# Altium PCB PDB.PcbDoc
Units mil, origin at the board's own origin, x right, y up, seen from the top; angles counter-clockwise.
Board outline 4930 x 2490 mil, 2 copper layers (Top Layer, Bottom Layer); 48 components, 33 nets, 136 pads, 994 vias.
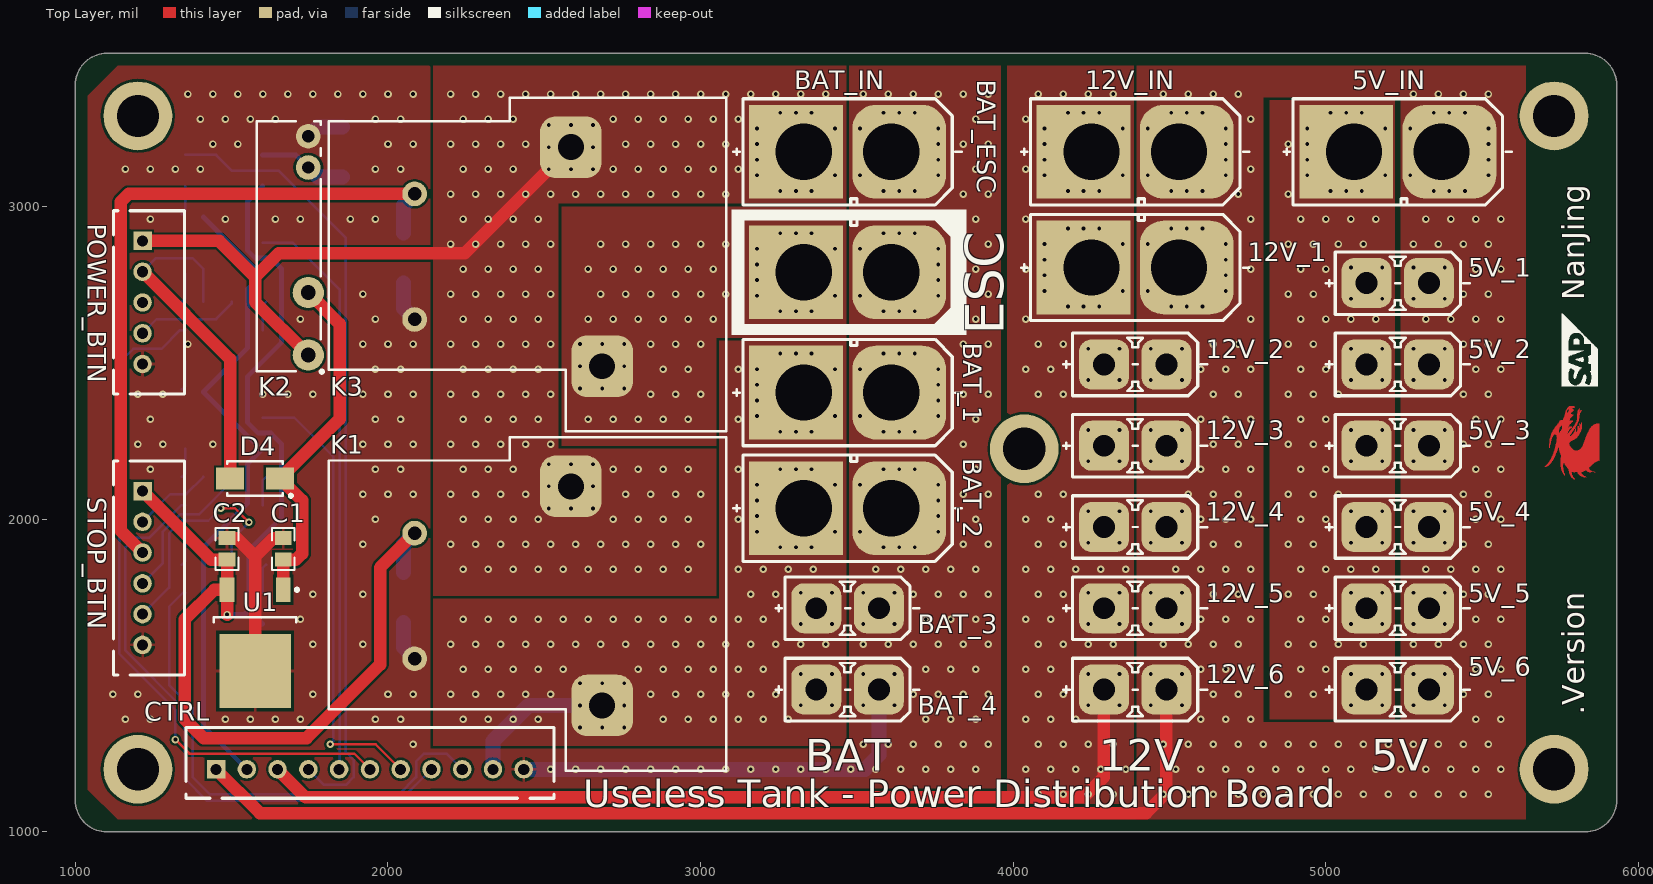
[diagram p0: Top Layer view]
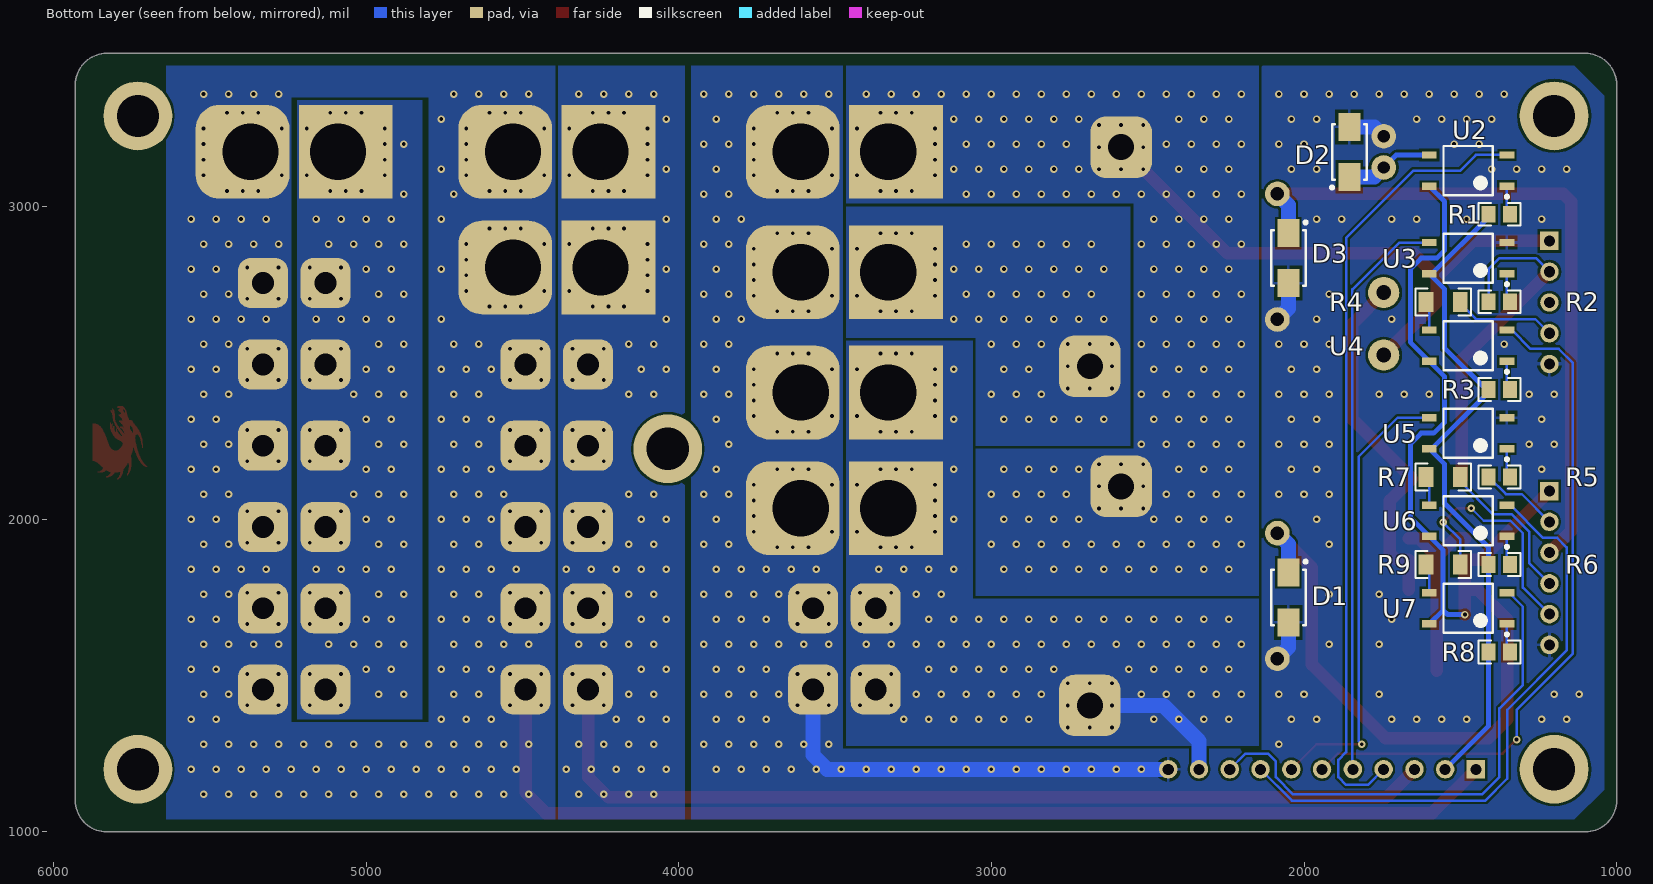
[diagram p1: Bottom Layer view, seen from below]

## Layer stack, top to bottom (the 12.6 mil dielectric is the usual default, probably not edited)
Top Solder: solder mask 0.4, Solder Resist, Dk 3.5
Top Layer: signal copper 1.4
Dielectric 1: dielectric 12.6, FR-4, Dk 4.8
Bottom Layer: signal copper 1.4
Bottom Solder: solder mask 0.4, Solder Resist, Dk 3.5

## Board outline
1100,1000 cw(c1100,1100) 1000,1100 1000,3390 cw(c1100,3390) 1100,3490 5830,3490 cw(c5830,3390) 5930,3390 5930,1100 cw(c5830,1100) 5830,1000

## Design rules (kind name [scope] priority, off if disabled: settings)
Clearance [All] p1: gap=8
ComponentClearance [All] p1: gap=8 collisioncheckmode=3 verticalgap=10 showdistances=FALSE
HoleSize [All] p1: absolutevalues=TRUE maxlimit=200 minlimit=12 maxpercent=80.000 minpercent=20.000
MinimumSolderMaskSliver [All] p1: minsoldermaskwidth=8
PolygonConnect "Full Connect" [IsVia OR (HasFootprint('XT60PB-M') OR HasFootprint('XT60PB-F') OR HasFootprint('XT30UPB-F') OR HasFootprint('HF105F-1') OR HasFootprint('HF49FD/xxx-1Hx1'))] p1: connectstyle=Direct reliefconductorwidth=10 reliefentries=4 polygonreliefangle="90 Angle" airgapwidth=10
PolygonConnect [All] p2: connectstyle=Relief reliefconductorwidth=10 reliefentries=4 polygonreliefangle="90 Angle" airgapwidth=10
RoutingVias [All] p1: holewidth=12 width=24 viastyle="Through Hole" minholewidth=12 minwidth=20 maxholewidth=50 maxwidth=80
SilkToSilkClearance SilkToSilkClearance_ignore [All] p1: silktosilkclearance=0
SilkToSilkClearance [All] p2: silktosilkclearance=8
SilkToSolderMaskClearance [IsPad] p1: minsilkscreentomaskgap=6 clearancetoexposedcopper=TRUE
SolderMaskExpansion SolderMaskExpansion_Via [IsVia] p1: expansion=-20
SolderMaskExpansion [All] p2: expansion=4
Width [All] p1: maxlimit=400 minlimit=8 preferedwidth=8
25 further rules are at their usual default settings.

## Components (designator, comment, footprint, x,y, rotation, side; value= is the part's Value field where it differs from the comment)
5V_1 "XT30/60/90" XT30UPB-F 5330,2755 r180 top
5V_2 "XT30/60/90" XT30UPB-F 5330,2495 r180 top
5V_3 "XT30/60/90" XT30UPB-F 5330,2235 r180 top
5V_4 "XT30/60/90" XT30UPB-F 5330,1975 r180 top
5V_5 "XT30/60/90" XT30UPB-F 5330,1715 r180 top
5V_6 "XT30/60/90" XT30UPB-F 5330,1455 r180 top
5V_IN "XT30/60/90" XT60PB-M 5370,3175 r180 top
12V_1 "XT30/60/90" XT60PB-F 4530,2805 r180 top
12V_2 "XT30/60/90" XT30UPB-F 4490,2495 r180 top
12V_3 "XT30/60/90" XT30UPB-F 4490,2235 r180 top
12V_4 "XT30/60/90" XT30UPB-F 4490,1975 r180 top
12V_5 "XT30/60/90" XT30UPB-F 4490,1715 r180 top
12V_6 "XT30/60/90" XT30UPB-F 4490,1455 r180 top
12V_IN "XT30/60/90" XT60PB-M 4530,3175 r180 top
BAT_1 "XT30/60/90" XT60PB-F 3610,2405 r180 top
BAT_2 "XT30/60/90" XT60PB-F 3610,2035 r180 top
BAT_3 "XT30/60/90" XT30UPB-F 3570,1715 r180 top
BAT_4 "XT30/60/90" XT30UPB-F 3570,1455 r180 top
BAT_ESC "XT30/60/90" XT60PB-F 3610,2790 r180 top
BAT_IN "XT30/60/90" XT60PB-M 3610,3175 r180 top
C1 "Cap" CAP0805_M 1665,1905 r270 top
C2 "Cap" CAP0805_M 1485,1905 r270 top
CTRL "XH2.54_11" XH_TH_TOP_11 1450,1200 r90 top
D1 "Diode US1M" DO-214AC 2050,1750 r270 bottom
D2 "Diode US1M" DO-214AC 1855,3175 r90 bottom
D3 "Diode US1M" DO-214AC 2050,2835 r270 bottom
D4 "Diode US1M" DO-214AC 1575,2130 r180 top
K1 "Relay HF105F-1" HF105F-1 2585,2105 r270 top
K2 "Relay HF49FD/012-1H11" HF49FD/xxx-1Hx1 1745,2525 r90 top
K3 "Relay HF105F-1" HF105F-1 2585,3190 r270 top
POWER_BTN "XH2.54_5" XH_TH_TOP_5 1215,2890 r0 top
R1 "Res2" RES0805_M 1375,2975 r180 bottom
R2 "Res2" RES0805_M 1375,2695 r0 bottom
R3 "Res2" RES0805_M 1375,2415 r180 bottom
R4 "Res2" RES1206_M 1555,2695 r180 bottom
R5 "Res2" RES0805_M 1375,2135 r180 bottom
R6 "Res2" RES0805_M 1375,1855 r180 bottom
R7 "Res2" RES1206_M 1555,2135 r0 bottom
R8 "Res2" RES0805_M 1375,1575 r180 bottom
R9 "Res2" RES1206_M 1555,1855 r180 bottom
STOP_BTN "XH2.54_6" XH_TH_TOP_6 1215,2090 r0 top
U1 "12V 1.5A" CJ7812_TO-252-2L 1575,1605 r270 top
U2 "Optoisolator TLP187" TLP187 1475,3115 r0 bottom
U3 "Optoisolator TLP187" TLP187 1475,2835 r0 bottom
U4 "Optoisolator TLP187" TLP187 1475,2555 r0 bottom
U5 "Optoisolator TLP187" TLP187 1475,2275 r0 bottom
U6 "Optoisolator TLP187" TLP187 1475,1995 r0 bottom
U7 "Optoisolator TLP187" TLP187 1475,1715 r0 bottom

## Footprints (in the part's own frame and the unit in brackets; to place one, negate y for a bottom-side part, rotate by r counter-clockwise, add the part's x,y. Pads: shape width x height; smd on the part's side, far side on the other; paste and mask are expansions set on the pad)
CAP0805_M [mm] "Chip Capacitor, 2-Leads, Body 2.00x1.25mm, IPC Medium Density"
  rect 1.15x1.35 smd: 1(-0.875,0) 2(0.875,0)
  silkscreen extent -1.7,-0.92 1.7,0.92, body extent -1.1,-0.67 1.1,0.67, height 0.7
CJ7812_TO-252-2L [mm] "D-PAK, 3-Pads, Body 6.20x6.71mm (max), IPC Medium Density"
  rect 2x1.2 smd: 1(-4.3,2.285) 3(-4.3,-2.285)
  rect 6x5.8 smd: 2(2.3,0)
  silkscreen extent -4.42,-3.35 -1.65,3.53, body extent -2.05,-3.35 4.15,3.35, height 2.38
DO-214AC [mil] "Molded Diode, 2-Leads, Body 4.25x2.67mm, IPC Medium Density"
  rect 90x70 smd: 1(-80,0) 2(80,0)
  silkscreen extent -119,-55 89,60, body extent -89,-55 89,55, height 95
HF49FD/xxx-1Hx1 [mm] "Relay HF49FD/xxx-1Hx1"
  round 2.54 hole 1.2: 1(0,0) 2(5.08,0)
  round 2 hole 1: 3(15.24,0) 4(17.78,0)
  silkscreen extent -1.48,-1.23 19,4.2, body extent -1.3,-1 19,4.2, height 12.8
HF105F-1 [mm] "Relay HF105F-1"
  rrect50% 5x5 hole 2.1: 1(0,0) 2(17.8,2.54)
  round 2 hole 1.1: 3(3.8,-12.7) 4(14,-12.7)
  silkscreen extent -4,-19.66 23.1,12.64, body extent -4,-19.66 23.1,12.64, height 20.2
RES0805_M [mm] "Chip Resistor, 2-Leads, Body 2.00x1.25mm, IPC Medium Density"
  rect 1.15x1.35 smd: 1(-0.875,0) 2(0.875,0)
  silkscreen extent -1.7,-0.92 1.7,0.92, body extent -1.1,-0.67 1.1,0.67, height 0.7
RES1206_M [mm] "Chip Resistor, 2-Leads, Body 3.13x1.55mm, IPC Medium Density"
  rect 1.2x1.65 smd: 1(-1.4,0) 2(1.4,0)
  silkscreen extent -2.25,-1.1 2.25,1.1, body extent -1.63,-0.82 1.63,0.82, height 0.7
TLP187 [mm] "SOP, 4-Leads, Body 3.75x4.60mm, Pitch 2.54mm, IPC Medium Density"
  rect 1.2x0.6 smd: 1(-3.15,1.27) 2(-3.15,-1.27) 3(3.15,-1.27) 4(3.15,1.27)
  silkscreen extent -3.27,-2 2,2.24, body extent -2.4,-2 2.4,2, height 2.3
XH_TH_TOP_5 [mm] "JST XH, Through Hole, Top Mount, 5Pin"
  rect 1.5x1.5 hole 0.9: 1(0,0)
  round 1.5 hole 0.9: 2(0,-2.5) 3(0,-5) 4(0,-7.5) 5(0,-10)
  silkscreen extent -2.35,-12.45 3.4,2.45
XH_TH_TOP_6 [mm] "JST XH, Through Hole, Top Mount, 6Pin"
  rect 1.5x1.5 hole 0.9: 1(0,0)
  round 1.5 hole 0.9: 2(0,-2.5) 3(0,-5) 4(0,-7.5) 5(0,-10) 6(0,-12.5)
  silkscreen extent -2.35,-14.95 3.4,2.45
XH_TH_TOP_11 [mm] "JST XH, Through Hole, Top Mount, 11Pin"
  rect 1.5x1.5 hole 0.9: 1(0,0)
  round 1.5 hole 0.9: 2(0,-2.5) 3(0,-5) 4(0,-7.5) 5(0,-10) 6(0,-12.5) 7(0,-15) 8(0,-17.5) 9(0,-20) 10(0,-22.5) 11(0,-25)
  silkscreen extent -2.35,-27.45 3.4,2.45
XT30UPB-F [mil]
  rrect50% 160x160 hole 70: GND(0,0) VCC(200,0)
  silkscreen extent -130,-100 330,100, body extent -100,-100 300,100, height 370
XT60PB-F [mil]
  rrect50% 300x300 hole 180 copper offset -25,0: GND(0,0)
  rect 300x300 hole 180 copper offset 25,0: VCC(280,0)
  silkscreen extent -225,-170 505,170, body extent -195,-170 475,170, height 630
XT60PB-M [mil]
  rrect50% 300x300 hole 180 copper offset -25,0: GND(0,0)
  rect 300x300 hole 180 copper offset 25,0: VCC(280,0)
  silkscreen extent -225,-170 505,170, body extent -195,-170 475,170, height 630

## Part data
C1 C2: "Capacitor"
D1 D2 D3 D4: "High Conductance Fast Diode"
K1 K3: "30A Single-Pole Single-Throw Relay"
K2: "5A Single-Pole Single-Throw Relay"
R1 R2 R3 R4 R5 R6 R7 R8 R9: "Resistor"
U1: library part CJ7812, "Voltage Regulator 12V 1.5A"
U2 U3 U4 U5 U6 U7: "4-Pin Phototransistor Optocoupler"

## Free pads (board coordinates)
  round 220 hole 135: ""(1200,1200) ""(1200,3290) ""(4035,2225) ""(5730,1200) ""(5730,3290)

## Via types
v1: diameter 24, hole 12, Top Layer to Bottom Layer, 962 vias
v2: diameter 24.02, hole 12, Top Layer to Bottom Layer, 32 vias

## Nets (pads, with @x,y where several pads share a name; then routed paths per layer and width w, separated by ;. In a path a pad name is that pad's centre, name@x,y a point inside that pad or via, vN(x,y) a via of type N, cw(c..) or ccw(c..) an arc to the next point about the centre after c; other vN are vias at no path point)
GND: 5V_1.GND 5V_2.GND 5V_3.GND 5V_4.GND 5V_5.GND 5V_6.GND 5V_IN.GND 12V_1.GND 12V_2.GND 12V_3.GND 12V_4.GND 12V_5.GND 12V_6.GND 12V_IN.GND CTRL.1 | length 3454.9
  Top Layer w40: CTRL.1 1590,1060 4425,1060 4490,1125 12V_6.GND
  other v1: 4480,1120 4560,1120 4640,1120 4720,1120 4800,1120 4880,1120 4960,1120 5040,1120 5120,1120 5200,1120 5280,1120 5360,1120 5440,1120 5520,1120 4520,1200 4600,1200 4680,1200 4760,1200 4840,1200 4920,1200 5000,1200 5080,1200 5160,1200 5240,1200 5320,1200 5400,1200 5480,1200 5560,1200 4480,1280 4560,1280 4640,1280 4720,1280 4800,1280 4880,1280 4960,1280 5040,1280 5120,1280 5200,1280 5280,1280 5360,1280 5440,1280 5520,1280 4600,1360 4680,1360 4760,1360 5480,1360 5560,1360 4440,1405 4540,1405 5280,1405 5380,1405 4640,1440 4720,1440 5440,1440 5520,1440 4440,1505 4540,1505 5280,1505 5380,1505 4600,1520 4680,1520 4760,1520 5480,1520 5560,1520 4480,1600 4560,1600 4640,1600 4720,1600 5280,1600 5360,1600 5440,1600 5520,1600 4440,1665 4540,1665 5280,1665 5380,1665 4600,1680 4680,1680 4760,1680 5480,1680 5560,1680 4640,1760 4720,1760 5440,1760 5520,1760 4440,1765 4540,1765 5280,1765 5380,1765 4520,1840 4600,1840 4680,1840 4760,1840 5320,1840 5400,1840 5480,1840 5560,1840 4640,1920 4720,1920 5440,1920 5520,1920 4440,1925 4540,1925 5280,1925 5380,1925 4600,2000 4680,2000 4760,2000 5480,2000 5560,2000 4440,2025 4540,2025 5280,2025 5380,2025 4560,2080 4640,2080 4720,2080 5440,2080 5520,2080 4600,2160 4680,2160 4760,2160 5480,2160 5560,2160 4440,2185 4540,2185 5280,2185 5380,2185 4640,2240 4720,2240 5440,2240 5520,2240 4440,2285 4540,2285 5280,2285 5380,2285 4600,2320 4680,2320 4760,2320 5480,2320 5560,2320 4640,2400 4720,2400 5440,2400 5520,2400 4440,2445 4540,2445 5280,2445 5380,2445 4600,2480 4680,2480 4760,2480 5480,2480 5560,2480 4440,2545 4540,2545 5280,2545 5380,2545 4640,2560 4720,2560 5440,2560 5520,2560 4760,2640 5320,2640 5400,2640 5480,2640 5560,2640 4505,2680 4555,2680 4605,2680 5280,2705 5380,2705 5440,2720 5520,2720 4430,2730 4680,2730 4680,2780 4760,2800 5480,2800 5560,2800 5280,2805 5380,2805 4680,2830 4430,2880 4680,2880 5280,2880 5360,2880 5440,2880 5520,2880 4505,2930 4555,2930 4605,2930 4760,2960 5320,2960 5400,2960 5480,2960 5560,2960 4720,3040 4505,3050 4555,3050 4605,3050 5345,3050 5395,3050 5445,3050 4430,3100 4680,3100 5270,3100 5520,3100 4760,3120 4680,3150 5520,3150 4680,3200 5520,3200 4430,3250 4680,3250 5270,3250 5520,3250 4760,3280 4505,3300 4555,3300 4605,3300 5345,3300 5395,3300 5445,3300 4480,3360 4560,3360 4640,3360 4720,3360 5280,3360 5360,3360 5440,3360 5520,3360
GND_BAT: BAT_1.GND BAT_2.GND BAT_3.GND BAT_4.GND BAT_ESC.GND BAT_IN.GND C1.1 C2.1 CTRL.11 D1.2 D2.2 D3.2 K1.4 K2.4 K3.4 POWER_BTN.5 STOP_BTN.6 U1.2 U3.2 U5.2 | length 2343
  Top Layer w40: C2.1 1515.55,1939.45 1575,1880 ; U1.2 1575,1880 ; C1.1 1634.45,1939.45 1575,1880
  Bottom Layer w48: K2.4 1775,3255 D2.2 ; D1.2 2050,1588.82 K1.4 ; D3.2 2050,2673.82 K3.4 ; CTRL.11 3525,1200 3570,1245 BAT_4.GND
  other v1: 2520,1200 2600,1200 2680,1200 2760,1200 2840,1200 2920,1200 3000,1200 3080,1200 3160,1200 3240,1200 3320,1200 3400,1200 3480,1200 3560,1200 3640,1200 3720,1200 3800,1200 3880,1200 2080,1280 3520,1280 3600,1280 3680,1280 3760,1280 3840,1280 3920,1280 1160,1360 1240,1360 1480,1360 1560,1360 1640,1360 1720,1360 1960,1360 2040,1360 3720,1360 3800,1360 3880,1360 3520,1405 3620,1405 1120,1440 1200,1440 1760,1440 2000,1440 2080,1440 3680,1440 3760,1440 3840,1440 3920,1440 3520,1505 3620,1505 3720,1520 3800,1520 3880,1520 1760,1600 1920,1600 3520,1600 3600,1600 3680,1600 3760,1600 3840,1600 3920,1600 3520,1665 3620,1665 1720,1680 3720,1680 3800,1680 3880,1680 1760,1760 1920,1760 3680,1760 3760,1760 3840,1760 3920,1760 3520,1765 3620,1765 3560,1840 3640,1840 3720,1840 3800,1840 3880,1840 3585,1910 3635,1910 3685,1910 1920,1920 3840,1920 3920,1920 3510,1960 3760,1960 1960,2000 3880,2000 3760,2010 3760,2060 1920,2080 2000,2080 2080,2080 3840,2080 3920,2080 3510,2110 3760,2110 1240,2160 1960,2160 2040,2160 3585,2160 3635,2160 3685,2160 3880,2160 1200,2240 1280,2240 1440,2240 1920,2240 2000,2240 2080,2240 3840,2240 3585,2280 3635,2280 3685,2280 1240,2320 1960,2320 2040,2320 3880,2320 3510,2330 3760,2330 3760,2380 1200,2400 1280,2400 1600,2400 1680,2400 1760,2400 1920,2400 2000,2400 2080,2400 3840,2400 3920,2400 3760,2430 1960,2480 2040,2480 3510,2480 3760,2480 3880,2480 3585,2530 3635,2530 3685,2530 1360,2560 1920,2560 2000,2560 2080,2560 3840,2560 3920,2560 1720,2640 1960,2640 3800,2640 3880,2640 3585,2665 3635,2665 3685,2665 3510,2715 3760,2715 1920,2720 3840,2720 3920,2720 3760,2765 3880,2800 3760,2815 3510,2865 3760,2865 3840,2880 3920,2880 3585,2915 3635,2915 3685,2915 1240,2960 1480,2960 1640,2960 1720,2960 1880,2960 1960,2960 3800,2960 3880,2960 3840,3040 3920,3040 3585,3050 3635,3050 3685,3050 3510,3100 3760,3100 1160,3120 1240,3120 1320,3120 1400,3120 1960,3120 2040,3120 3880,3120 3760,3150 1440,3200 1520,3200 2000,3200 2080,3200 3760,3200 3840,3200 3920,3200 3510,3250 3760,3250 1400,3280 1480,3280 1560,3280 1640,3280 1960,3280 2040,3280 3880,3280 3585,3300 3635,3300 3685,3300 1360,3360 1440,3360 1520,3360 1600,3360 1680,3360 1760,3360 1840,3360 1920,3360 2000,3360 2080,3360 3520,3360 3600,3360 3680,3360 3760,3360 3840,3360 3920,3360
NetBAT_ESC_VCC: BAT_ESC.VCC K3.2
  other v1: 2640,2320 2720,2320 2800,2320 2880,2320 2960,2320 2840,2400 2920,2400 3000,2400 2880,2480 2960,2480 2840,2560 2920,2560 3000,2560 2640,2640 2720,2640 2800,2640 2880,2640 2960,2640 3040,2640 3120,2640 3255,2665 3305,2665 3355,2665 3180,2715 3430,2715 2680,2720 2760,2720 2840,2720 2920,2720 3000,2720 3080,2720 3180,2765 2640,2800 2720,2800 2800,2800 2880,2800 2960,2800 3040,2800 3120,2800 3180,2815 3180,2865 3430,2865 2680,2880 2760,2880 2840,2880 2920,2880 3000,2880 3080,2880 3255,2915 3305,2915 3355,2915
  other v2: 2614.13,2418.35 2685,2418.35 2755.87,2418.35 2614.13,2489.21 2755.87,2489.21 2614.13,2560.08 2685,2560.08 2755.87,2560.08
NetC1_2: C1.2 D4.1 K2.2 U1.1 | length 1148.4
  Top Layer w40: U1.1 U1.1 C1.2 1705.55,1870.55 1725,1890 1725,2060 D4.1 1845,2320 1845,2625 K2.2
NetD2_1: D2.1 K2.3 U2.3 | length 285
  Bottom Layer w16: U2.3 1705,3165 K2.3
  Bottom Layer w48: K2.3 1775,3095 D2.1
NetR1_2: R1.2 U2.1 | length 94.3
  Bottom Layer w8: R1.2 1350.98,2985.43 U2.1
NetR2_1: R2.1 U3.1 | length 94.3
  Bottom Layer w8: R2.1 1350.98,2705.43 U3.1
NetR3_2: R3.2 U4.1 | length 94.3
  Bottom Layer w8: R3.2 1350.98,2425.43 U4.1
NetR4_1: R4.1 U4.3 | length 94.6
  Bottom Layer w8: U4.3 1599.02,2683.9 R4.1
NetR5_2: R5.2 U5.1 | length 94.3
  Bottom Layer w8: R5.2 1350.98,2145.43 U5.1
NetR6_2: R6.2 U6.1 | length 94.3
  Bottom Layer w8: R6.2 1350.98,1865.43 U6.1
NetR7_2: R7.2 U6.3 | length 94.6
  Bottom Layer w8: U6.3 1599.02,2123.9 R7.2
NetR8_2: R8.2 U7.1 | length 94.3
  Bottom Layer w8: R8.2 1350.98,1585.43 U7.1
NetR9_1: R9.1 U7.3 | length 94.6
  Bottom Layer w8: U7.3 1599.02,1843.9 R9.1
PWR_BTN_DET: CTRL.5 U3.3 | length 1843.7
  Bottom Layer w8: U3.3 1695,2885 1845,2735 1845,1201.3 CTRL.5
PWR_BTN_DOWN: D4.2 POWER_BTN.2 R2.2 | length 1109.8
  Top Layer w40: POWER_BTN.2 1495,2511.57 D4.2
  Bottom Layer w8: POWER_BTN.2 1258.43,2835 1375,2835 1409.45,2800.55 R2.2
PWR_BTN_UP: POWER_BTN.3
PWR_CTRL: CTRL.4 U2.2 | length 2534.9
  Bottom Layer w8: U2.2 1450,3165 1500,3115 1650,3115 1865,2900 1865,1255 1890,1230 1890,1175 1865,1150 1795.28,1150 CTRL.4
PWR_LED: POWER_BTN.4 R4.2 | length 329.4
  Bottom Layer w8: POWER_BTN.4 1260.28,2640 1450,2640 1499.88,2689.88 R4.2
PWR_LED_CTRL: CTRL.6 U4.2 | length 2195.5
  Top Layer w8: v1(1320,1295) 1365,1250 1892.13,1250 CTRL.6
  Bottom Layer w8: v1(1320,1295) 1320,1390 1140,1570 1140,2500 1185,2545 1275,2545 1335,2605 U4.2
STOP_BTN_DET: CTRL.7 U5.3 | length 1460.6
  Top Layer w8: v1(1815,1280) 1960.55,1280 CTRL.7
  Bottom Layer w8: U5.3 1700,2325 1825,2200 1825,1290 v1(1815,1280)
STOP_BTN_DOWN: R5.1 STOP_BTN.2 | length 253.9
  Bottom Layer w8: STOP_BTN.2 1303.43,2080 1354.45,2080 R5.1
STOP_BTN_UP: D3.1 K3.3 STOP_BTN.3 | length 2241.3
  Top Layer w40: STOP_BTN.3 1145,1963.15 1145,3015 1170.39,3040.39 K3.3
  Bottom Layer w48: D3.1 2050,3005.39 K3.3
STOP_LED_G: R7.1 STOP_BTN.4 | length 493.4
  Bottom Layer w8: STOP_BTN.4 1280,1859.72 1280,1960 1335,2015 1395,2015 1499.88,2119.88 R7.1
STOP_LED_G_CTRL: CTRL.8 U6.2 | length 1925
  Bottom Layer w8: U6.2 1340,2045 1235,1940 1190,1940 1160,1910 1160,1580 1350,1390 1350,1170 1420,1100 2038.98,1100 CTRL.8
STOP_LED_R: R9.2 STOP_BTN.5 | length 768.5
  Top Layer w8: v1(1465,2035) 1510,2035 v1(1555,1990)
  Bottom Layer w8: STOP_BTN.5 1300,1781.3 1300,1955 1340,1995 1425,1995 v1(1465,2035) ; R9.2@1499.88,1839.88 R9.2@1499.88,1849.88 ; R9.2 1499.88,1934.88 v1(1555,1990)
STOP_LED_R_CTRL: CTRL.9 U7.2 | length 1634.7
  Bottom Layer w8: U7.2 1345,1765 1300,1720 1300,1470 1375,1395 1375,1175 1430,1120 2035,1120 2090,1175 2090,1225 2115,1250 2187.4,1250 CTRL.9
VCC_5V: 5V_1.VCC 5V_2.VCC 5V_3.VCC 5V_4.VCC 5V_5.VCC 5V_6.VCC 5V_IN.VCC
  other v1: 5080,1405 5180,1405 4880,1440 4960,1440 5080,1505 5180,1505 4920,1520 5000,1520 4880,1600 4960,1600 5040,1600 5120,1600 5080,1665 5180,1665 4920,1680 5000,1680 4880,1760 4960,1760 5080,1765 5180,1765 4920,1840 5000,1840 5080,1840 5160,1840 4880,1920 4960,1920 5080,1925 5180,1925 4920,2000 5000,2000 5080,2025 5180,2025 4880,2080 4960,2080 5040,2080 4920,2160 5000,2160 5080,2185 5180,2185 4880,2240 4960,2240 5080,2285 5180,2285 4920,2320 5000,2320 4880,2400 4960,2400 5040,2400 5080,2445 5180,2445 4920,2480 5000,2480 5080,2545 5180,2545 4880,2560 4960,2560 4920,2640 5000,2640 5080,2640 5160,2640 5080,2705 5180,2705 4880,2720 4960,2720 4920,2800 5000,2800 5080,2805 5180,2805 4880,2880 4960,2880 5040,2880 5120,2880 4920,2960 5000,2960 5080,2960 5160,2960 4880,3040 5015,3050 5065,3050 5115,3050 4940,3100 5190,3100 4940,3150 4880,3200 4940,3200 4940,3250 5190,3250 5015,3300 5065,3300 5115,3300
VCC_12V: 12V_1.VCC 12V_2.VCC 12V_3.VCC 12V_4.VCC 12V_5.VCC 12V_6.VCC 12V_IN.VCC CTRL.3 | length 2987.4
  Top Layer w40: CTRL.3 1736.85,1110 4225,1110 4290,1175 12V_6.VCC
  other v1: 4080,1120 4160,1120 4240,1120 4320,1120 4040,1200 4120,1200 4200,1200 4280,1200 4360,1200 4080,1280 4160,1280 4240,1280 4320,1280 4040,1360 4120,1360 4200,1360 4240,1405 4340,1405 4080,1440 4160,1440 4240,1505 4340,1505 4040,1520 4120,1520 4080,1600 4160,1600 4240,1600 4320,1600 4240,1665 4340,1665 4040,1680 4120,1680 4080,1760 4160,1760 4240,1765 4340,1765 4040,1840 4120,1840 4200,1840 4280,1840 4360,1840 4080,1920 4160,1920 4240,1925 4340,1925 4040,2000 4120,2000 4240,2025 4340,2025 4080,2080 4160,2080 4240,2185 4340,2185 4240,2285 4340,2285 4080,2400 4160,2400 4240,2445 4340,2445 4040,2480 4120,2480 4240,2545 4340,2545 4080,2560 4160,2560 4040,2640 4175,2680 4225,2680 4275,2680 4100,2730 4350,2730 4100,2780 4040,2800 4100,2830 4100,2880 4350,2880 4175,2930 4225,2930 4275,2930 4040,2960 4175,3050 4225,3050 4275,3050 4100,3100 4350,3100 4040,3120 4100,3150 4100,3200 4100,3250 4350,3250 4040,3280 4175,3300 4225,3300 4275,3300 4080,3360 4160,3360 4240,3360 4320,3360
VCC_BAT: BAT_1.VCC BAT_2.VCC BAT_3.VCC BAT_4.VCC CTRL.10 K1.2 | length 487
  Bottom Layer w48: CTRL.10 2335.83,1290.83 2449.21,1404.21 v2(2614.13,1404.21) K1.2
  other v1: 2240,1360 2320,1360 2400,1360 2480,1360 2880,1360 2960,1360 3040,1360 3120,1360 3200,1360 3280,1360 3320,1405 3420,1405 2200,1440 2280,1440 2360,1440 2440,1440 2520,1440 2840,1440 2920,1440 3000,1440 3080,1440 3160,1440 3240,1440 3320,1505 3420,1505 2240,1520 2320,1520 2400,1520 2480,1520 2560,1520 2800,1520 2880,1520 2960,1520 3040,1520 3120,1520 3200,1520 2200,1600 2280,1600 2360,1600 2440,1600 2520,1600 2600,1600 2680,1600 2760,1600 2840,1600 2920,1600 3000,1600 3080,1600 3160,1600 3240,1600 3320,1600 3400,1600 3320,1665 3420,1665 2240,1680 2320,1680 2400,1680 2480,1680 2560,1680 2640,1680 2720,1680 2800,1680 2880,1680 2960,1680 3040,1680 3120,1680 3200,1680 3160,1760 3240,1760 3320,1765 3420,1765 3120,1840 3200,1840 3280,1840 3360,1840 3255,1910 3305,1910 3355,1910 3180,1960 3430,1960 3120,2000 3180,2010 3180,2060 3180,2110 3430,2110 3120,2160 3255,2160 3305,2160 3355,2160 3255,2280 3305,2280 3355,2280 3120,2320 3180,2330 3430,2330 3180,2380 3180,2430 3120,2480 3180,2480 3430,2480 3255,2530 3305,2530 3355,2530
  other v2: 2614.13,1333.35 2685,1333.35 2755.87,1333.35 2755.87,1404.21 2614.13,1475.08 2685,1475.08 2755.87,1475.08
VCC_BAT_SRC: BAT_IN.VCC K1.1 K2.1 K3.1 POWER_BTN.1 | length 1909.9
  Top Layer w40: POWER_BTN.1 1460,2890 1575,2775 ; K2.1 1575,2695 1575,2775 ; K3.1 v2(2514.13,3119.13) 2245,2850 1650,2850 1575,2775
  other v1: 2240,1840 2320,1840 2400,1840 2480,1840 2560,1840 2640,1840 2720,1840 2800,1840 2880,1840 2960,1840 2200,1920 2280,1920 2360,1920 2440,1920 2520,1920 2600,1920 2680,1920 2760,1920 2840,1920 2920,1920 3000,1920 2240,2000 2320,2000 2400,2000 2480,2000 2720,2000 2800,2000 2880,2000 2960,2000 2200,2080 2280,2080 2360,2080 2440,2080 2760,2080 2840,2080 2920,2080 3000,2080 2240,2160 2320,2160 2400,2160 2720,2160 2800,2160 2880,2160 2960,2160 2200,2240 2280,2240 2360,2240 2440,2240 2520,2240 2240,2320 2320,2320 2400,2320 2480,2320 2200,2400 2280,2400 2360,2400 2440,2400 2520,2400 2240,2480 2320,2480 2400,2480 2480,2480 2200,2560 2280,2560 2360,2560 2440,2560 2520,2560 2240,2640 2320,2640 2400,2640 2480,2640 2200,2720 2280,2720 2360,2720 2440,2720 2520,2720 2240,2800 2320,2800 2400,2800 2480,2800 2200,2880 2280,2880 2360,2880 2440,2880 2520,2880 2240,2960 2320,2960 2400,2960 2480,2960 2200,3040 2280,3040 2360,3040 2440,3040 2520,3040 2600,3040 2680,3040 2760,3040 2840,3040 2920,3040 3000,3040 3080,3040 3255,3050 3305,3050 3355,3050 3180,3100 3430,3100 2240,3120 2320,3120 2400,3120 2720,3120 2800,3120 2880,3120 2960,3120 3040,3120 3120,3120 3180,3150 2200,3200 2280,3200 2360,3200 2440,3200 2760,3200 2840,3200 2920,3200 3000,3200 3080,3200 3180,3200 3180,3250 3430,3250 2240,3280 2320,3280 2400,3280 2720,3280 2800,3280 2880,3280 2960,3280 3040,3280 3120,3280 3255,3300 3305,3300 3355,3300 2200,3360 2280,3360 2360,3360 2440,3360 2520,3360 2600,3360 2680,3360 2760,3360 2840,3360 2920,3360 3000,3360 3080,3360 3160,3360 3240,3360 3320,3360 3400,3360
  other v2: 2514.13,2034.13 2585,2034.13 2655.87,2034.13 2514.13,2105 2655.87,2105 2514.13,2175.87 2585,2175.87 2655.87,2175.87 2585,3119.13 2655.87,3119.13 2514.13,3190 2655.87,3190 2514.13,3260.87 2585,3260.87 2655.87,3260.87
VCC_MCU: CTRL.2 R1.1 R3.1 R6.1 R8.1 U3.4 U5.4 | length 2147.6
  Bottom Layer w16: R1.1@1409.45,2966.61 1591.06,2785 U3.4 1550,2735.98 1550,2547.16 1409.45,2406.61 1591.06,2225 U5.4 1550,2175.98 1550,2050 1409.45,1909.45 R6.1 R8.1 1409.45,1338.98 CTRL.2
VCC_PDB_12V: C2.2 D1.1 K1.3 STOP_BTN.1 U1.3 U2.4 U4.4 U6.4 U7.4 | length 4130.8
  Top Layer w40: STOP_BTN.1 1434.45,1870.55 C2.2 ; v1(1485.04,1695) U1.3 ; C2.2@1485.04,1870.51 U1.3 ; K1.3 1975,1845.39 1975,1535 1740,1300 1410,1300 1350,1360 1350,1680 1444.29,1774.29 U1.3
  Bottom Layer w16: v1(1485.04,1695) 1540.98,1695 1555,1709.02 ; U7.4 1555,1709.02 ; U2.4 1550,3015.98 1550,2860 1575,2835 1625,2835 1660,2800 1660,2565.98 U4.4 1550,2455.98 1550,2310 1585,2275 1625,2275 1660,2240 1660,2005.98 U6.4 1555,1900.98 1555,1709.02
  Bottom Layer w48: D1.1 2050,1920.39 K1.3

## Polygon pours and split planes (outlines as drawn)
GND_BAT on Top Layer "Top Layer-PDB_GND" (solid, pour order 26): 2135,1040 1135,1040 1040,1135 1040,3355 1135,3450 2135,3450
NetBAT_ESC_VCC on Top Layer "Top Layer-NetBAT_ESC_VCC" (solid, pour order 22): 3465,3000 3465,2580 3050,2580 3050,2235 2555,2235 2555,3000
VCC_BAT_SRC on Top Layer "Top Layer-VCC_BAT_SRC" (solid, pour order 20): 3465,3010 3465,3450 2145,3450 2145,1755 3050,1755 3050,2225 2545,2225 2545,3010
VCC_BAT on Top Layer "Top Layer-VCC_BAT" (solid, pour order 23): 3465,2570 3465,1275 2145,1275 2145,1745 3060,1745 3060,2570
VCC_12V on Top Layer "Top Layer-Net12V_VCC" (solid, pour order 29): 4385,3450 3980,3450 3980,1090 4385,1090
GND on Top Layer "Top Layer-Net12V_GND" (solid, pour order 31): 4800,1350 5250,1350 5250,1040 4395,1040 4395,3450 5250,3450 5250,3350 4800,3350
VCC_5V on Top Layer "Top Layer-Net5V_VCC" (solid, pour order 33): 5220,3340 4820,3340 4820,1360 5220,1360
GND on Top Layer "Top Layer-Net5V_GND" (solid, pour order 35): 5240,1040 5640,1040 5640,3450 5240,3450
GND_BAT on Top Layer "Top Layer-GND_BAT" (solid, pour order 27): 3475,3450 3960,3450 3960,1140 2120,1140 2120,1265 3475,1265
GND_BAT on Bottom Layer "Bottom Layer-PDB_GND" (solid, pour order 24): 2135,1040 1135,1040 1040,1135 1040,3355 1135,3450 2135,3450
NetBAT_ESC_VCC on Bottom Layer "Bottom Layer-NetBAT_ESC_VCC" (solid, pour order 21): 3465,3000 3465,2580 3050,2580 3050,2235 2555,2235 2555,3000
VCC_BAT_SRC on Bottom Layer "Bottom Layer-VCC_BAT_SRC" (solid, pour order 19): 3465,3010 3465,3450 2145,3450 2145,1755 3050,1755 3050,2225 2545,2225 2545,3010
VCC_BAT on Bottom Layer "Bottom Layer-VCC_BAT" (solid, pour order 25): 3465,2570 3465,1275 2145,1275 2145,1745 3060,1745 3060,2570
GND_BAT on Bottom Layer "Bottom Layer-GND_BAT" (solid, pour order 28): 3475,3450 3960,3450 3960,1040 2120,1040 2120,1265 3475,1265
VCC_12V on Bottom Layer "Bottom Layer-Net12V_VCC" (solid, pour order 30): 4385,3450 3980,3450 3980,1040 4385,1040
GND on Bottom Layer "Bottom Layer-Net12V_GND" (solid, pour order 32): 4800,1350 5250,1350 5250,1040 4395,1040 4395,3450 5250,3450 5250,3350 4800,3350
VCC_5V on Bottom Layer "Bottom Layer-Net5V_VCC" (solid, pour order 34): 5220,3340 4820,3340 4820,1360 5220,1360
GND on Bottom Layer "Bottom Layer-Net5V_GND" (solid, pour order 36): 5240,3450 5640,3450 5640,1040 5240,1040
no net on Top Overlay "Top Overlay-ESC" (solid): 3850,2990 3100,2990 3100,2590 3850,2590

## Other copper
Top Layer:
  region: 1586 vertices and 2 holes, not listed, extent 5700.25,2127.61 5875,2361.82

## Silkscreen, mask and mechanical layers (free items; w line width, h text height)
Top Overlay:
  drawing of 4 lines, arcs and shapes, not listed
  text "NanJing" at 5850,2700 h120 r90
  text "ESC" at 4010,2590 h210 r90
  text ".Version" at 5850,1375 h120 r90
  text "BAT" at 3335,1195 h100
  text "12V" at 4275,1195 h100
  text "5V" at 5145,1195 h100
  text "Useless Tank - Power Distribution Board" at 2625,1050 h150
Mechanical 1:
  the board outline again, w10
Drill Drawing:
  circle w1: c6150.62,2427.5 r25
  circle w1: c6150.62,1227.5 r15
  circle w1: c6150.62,1227.5 r25
  lines w1: 6125.62,1365 6138.12,1365 6138.12,1352.5 6163.12,1352.5 6163.12,1365 6175.62,1365 6175.62,1390 6163.12,1390 6163.12,1402.5 6138.12,1402.5 6138.12,1390 6125.62,1390 6125.62,1365 ; 6125.62,1502.5 6175.62,1502.5 6175.62,1552.5 6125.62,1552.5 6125.62,1502.5 ; 6125.62,1665 6138.12,1665 6150.62,1652.5 6163.12,1665 6175.62,1665 6163.12,1677.5 6175.62,1690 6163.12,1690 6150.62,1702.5 6138.12,1690 6125.62,1690 6138.12,1677.5 6125.62,1665 ; 6125.62,1802.5 6125.62,1815 6138.12,1827.5 6125.62,1840 6125.62,1852.5 6138.12,1852.5 6150.62,1840 6163.12,1852.5 6175.62,1852.5 6175.62,1840 6163.12,1827.5 6175.62,1815 6175.62,1802.5 6163.12,1802.5 6150.62,1815 6138.12,1802.5 6125.62,1802.5 ; 6125.62,1952.5 6175.62,1952.5 6175.62,2002.5 6125.62,2002.5 6125.62,1952.5 ; 6125.62,2102.5 6150.62,2115 6175.62,2102.5 6163.12,2127.5 6175.62,2152.5 6150.62,2140 6125.62,2152.5 6138.12,2127.5 6125.62,2102.5 ; 6125.62,2277.5 6150.62,2252.5 6175.62,2277.5 6150.62,2302.5 6125.62,2277.5 ; 6135.62,1962.5 6165.62,1962.5 6165.62,1992.5 6135.62,1992.5 6135.62,1962.5
  lines w15: 6057.5,1157.5 9936.47,1157.5 ; 6057.5,2507.5 9936.47,2507.5 ; 6608.38,1007.5 6608.38,2657.5 ; 7306.19,1007.5 7306.19,2657.5 ; 8651.79,1007.5 8651.79,2657.5 ; 9157.67,1007.5 9157.67,2657.5 ; 6057.5,1007.5 9936.47,1007.5 9936.47,2657.5 6057.5,2657.5 6057.5,1007.5
  text "Symbol" at 6147.5,2552.5 h72
  text "Hit Count" at 6653.38,2552.5 h72
  text "Finished Hole Size" at 7351.19,2552.5 h72
  text "Plated" at 8696.79,2552.5 h72
  text "Hole Type" at 9202.67,2552.5 h72
  text "2" at 6653.38,2402.5 h60
  text "39.37mil (1.000mm)" at 7351.19,2402.5 h60
  text "PTH" at 8696.79,2402.5 h60
  text "Round" at 9202.67,2402.5 h60
  text "2" at 6653.38,2252.5 h60
  text "47.24mil (1.200mm)" at 7351.19,2252.5 h60
  text "PTH" at 8696.79,2252.5 h60
  text "Round" at 9202.67,2252.5 h60
  text "4" at 6653.38,2102.5 h60
  text "43.31mil (1.100mm)" at 7351.19,2102.5 h60
  text "PTH" at 8696.79,2102.5 h60
  text "Round" at 9202.67,2102.5 h60
  text "4" at 6653.38,1952.5 h60
  text "82.68mil (2.100mm)" at 7351.19,1952.5 h60
  text "PTH" at 8696.79,1952.5 h60
  text "Round" at 9202.67,1952.5 h60
  text "5" at 6653.38,1802.5 h60
  text "135.00mil (3.429mm)" at 7351.19,1802.5 h60
  text "PTH" at 8696.79,1802.5 h60
  text "Round" at 9202.67,1802.5 h60
  text "14" at 6653.38,1652.5 h60
  text "180.00mil (4.572mm)" at 7351.19,1652.5 h60
  text "PTH" at 8696.79,1652.5 h60
  text "Round" at 9202.67,1652.5 h60
  text "22" at 6653.38,1502.5 h60
  text "35.43mil (0.900mm)" at 7351.19,1502.5 h60
  text "PTH" at 8696.79,1502.5 h60
  text "Round" at 9202.67,1502.5 h60
  text "26" at 6653.38,1352.5 h60
  text "70.00mil (1.778mm)" at 7351.19,1352.5 h60
  text "PTH" at 8696.79,1352.5 h60
  text "Round" at 9202.67,1352.5 h60
  text "994" at 6653.38,1202.5 h60
  text "12.00mil (0.305mm)" at 7351.19,1202.5 h60
  text "PTH" at 8696.79,1202.5 h60
  text "Round" at 9202.67,1202.5 h60
  text "1073 Total" at 6653.38,1052.5 h60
